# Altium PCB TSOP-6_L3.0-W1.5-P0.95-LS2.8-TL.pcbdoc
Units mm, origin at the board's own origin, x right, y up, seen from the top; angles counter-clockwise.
Board outline 16.1 x 16.06 mm, 2 copper layers (Top Layer, Bottom Layer), stack 0 mm thick; 1 components, 0 nets, 6 pads, 0 vias.
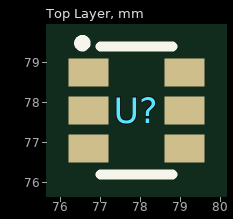
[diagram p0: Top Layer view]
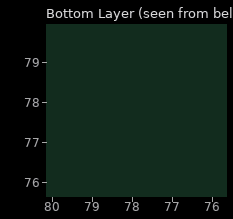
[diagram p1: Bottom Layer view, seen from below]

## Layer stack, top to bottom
Top Layer: signal copper (thickness not stored)
Bottom Layer: signal copper (thickness not stored)

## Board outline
85.95,69.85 69.85,69.85 69.85,85.908 85.95,85.908

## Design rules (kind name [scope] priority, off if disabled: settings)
PasteMaskExpansion "Paste Mask Expansion" [All] p1: expansion=0
SolderMaskExpansion "Solder Mask Expansion" [IsVia] p1: expansion=-25.4 istentingtop=TRUE
SolderMaskExpansion "Solder Mask Expansion" [All] p2: expansion=0.051 istentingtop=FALSE

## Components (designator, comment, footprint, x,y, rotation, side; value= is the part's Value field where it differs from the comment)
U? "" TSOP-6_L3.0-W1.5-P0.95-LS2.8-TL 77.9,77.8 r0 top

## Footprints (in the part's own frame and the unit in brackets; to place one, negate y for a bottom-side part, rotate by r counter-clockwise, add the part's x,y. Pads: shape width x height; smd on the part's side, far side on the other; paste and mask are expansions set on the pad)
TSOP-6_L3.0-W1.5-P0.95-LS2.8-TL [mm]
  rect 1x0.7 smd: 1(-1.2,0.95) 2(-1.2,0) 3(-1.2,-0.95) 4(1.2,-0.95) 5(1.2,0) 6(1.2,0.95)
  silkscreen extent -1.43,-1.6 0.9,1.76

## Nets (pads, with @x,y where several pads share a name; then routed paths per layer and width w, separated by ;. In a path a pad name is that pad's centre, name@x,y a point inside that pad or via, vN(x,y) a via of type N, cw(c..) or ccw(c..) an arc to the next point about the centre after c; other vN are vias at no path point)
pads on no net: U?.1 U?.2 U?.3 U?.4 U?.5 U?.6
